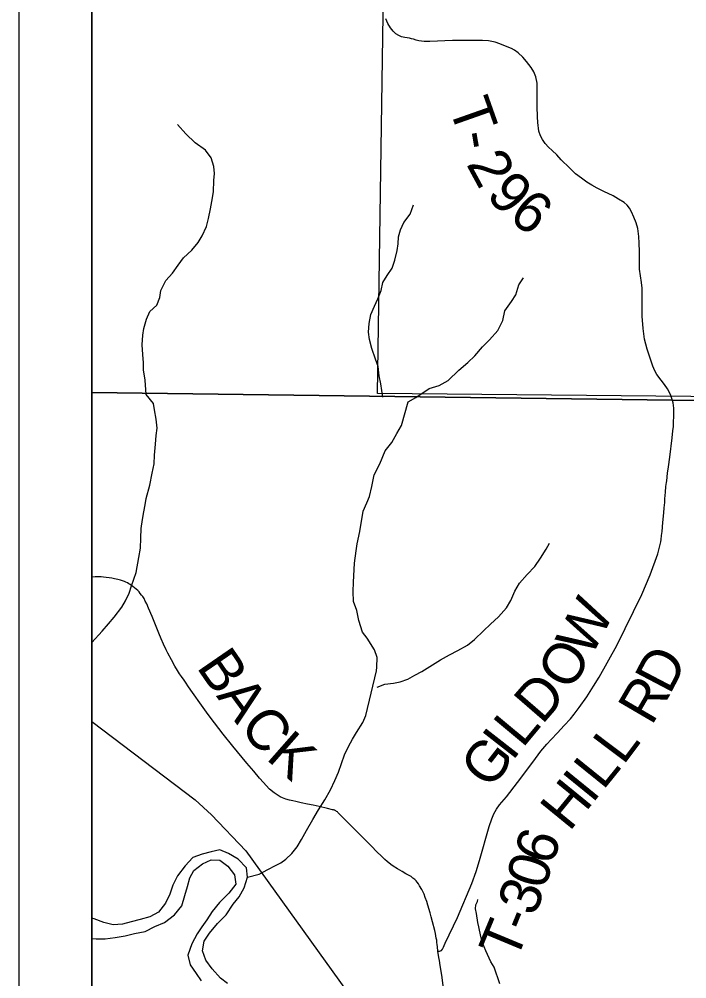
# Model space of a CAD drawing. Extents: x 0 to 34, y -8.9 to 22.
# Drawn here: x 23.617 to 24.538, y 18.53 to 19.856 of the extents above; entities that cross this region are included whole.
import ezdxf

# ---------------------------------------------------------------- set-up
doc = ezdxf.new("R2010")
doc.units = 0
for name, color, linetype in [('GM_X_Corporation', 7, 'Continuous'), ('GM_X_Major_River', 7, 'Continuous'), ('GM_X_Minor_River', 7, 'Continuous'), ('GM_X_Rail_Line', 7, 'Continuous'), ('GM_X_Township_Road', 7, 'Continuous'), ('GM_X_Township_Road_Text', 7, 'Continuous'), ('SH_Data', 7, 'Continuous')]:
    doc.layers.add(name, color=color, linetype=linetype)

msp = doc.modelspace()

# ---------------------------------------------------------------- linework, layer by layer
at = {"layer": 'GM_X_Corporation'}
for points in [[(30.5167, 21.4), (23.7167, 21.4), (23.7167, 19.34), (24.5181, 19.3295), (25.0504, 19.3237), (25.1066, 19.3232), (25.1068, 18.8675), (25.1136, 18.8385), (25.1229, 18.6966), (25.125, 18.6354), (25.1216, 18.6194), (25.1124, 18.5932), (25.1045, 18.3117), (25.2083, 18.3108), (25.7381, 18.312), (26.1399, 18.3037), (26.1391, 17.8847), (26.1361, 17.3278)], [(23.7167, 21.3241), (23.7167, 19.34), (24.5181, 19.3295), (25.0504, 19.3237), (25.1066, 19.3232), (25.1068, 18.8675), (25.1136, 18.8385), (25.1229, 18.6966), (25.125, 18.6354), (25.1216, 18.6194), (25.1124, 18.5932), (25.1045, 18.3117), (25.2083, 18.3108), (25.7381, 18.312), (26.1399, 18.3037), (26.1391, 17.8847), (26.1361, 17.3278)], [(26.1361, 17.3278), (26.1391, 17.8847), (26.1399, 18.3037), (25.7381, 18.312), (25.2083, 18.3108), (25.1045, 18.3117), (25.1124, 18.5932), (25.1216, 18.6194), (25.125, 18.6354), (25.1229, 18.6966), (25.1136, 18.8385), (25.1068, 18.8675), (25.1066, 19.3232), (25.0504, 19.3237), (24.5181, 19.3295), (23.7167, 19.34), (23.7167, 14.6)]]:
    msp.add_lwpolyline(points, dxfattribs=at)
for points in [[(25.1285, 20.3218), (25.1197, 19.3292), (24.1109, 19.3387), (24.1258, 20.3236)], [(23.7167, 19.34), (23.7167, 15.9913), (24.0651, 15.9828), (24.2771, 15.9807), (24.8268, 15.964), (25.6785, 15.9418), (25.7922, 15.939), (26.1186, 15.9366), (26.135, 17.3055), (26.1361, 17.3278), (26.1391, 17.8847), (26.1399, 18.3037), (25.7381, 18.312), (25.2083, 18.3108), (25.1045, 18.3117), (25.1124, 18.5932), (25.1216, 18.6194), (25.125, 18.6354), (25.1229, 18.6966), (25.1136, 18.8385), (25.1068, 18.8675), (25.1066, 19.3232), (25.0504, 19.3237), (24.5181, 19.3295)]]:
    msp.add_lwpolyline(points, close=True, dxfattribs=at)
at = {"layer": 'GM_X_Major_River'}
for points in [[(23.9043, 18.5242), (23.8944, 18.5313), (23.8828, 18.544), (23.874, 18.5564), (23.8696, 18.5693), (23.8721, 18.5822), (23.8791, 18.5937), (23.8903, 18.6067), (23.9023, 18.619), (23.9119, 18.6335), (23.9202, 18.6435), (23.9272, 18.6561), (23.9319, 18.671), (23.9302, 18.6835), (23.9187, 18.6958), (23.9057, 18.7036), (23.8935, 18.7084), (23.8814, 18.7056), (23.8693, 18.7024), (23.8565, 18.698), (23.8456, 18.6865), (23.8352, 18.6727), (23.8289, 18.6597), (23.8246, 18.6472), (23.8187, 18.6349), (23.809, 18.6227), (23.7969, 18.6161), (23.7837, 18.6125), (23.7712, 18.6093), (23.7592, 18.6057), (23.7463, 18.6048), (23.7333, 18.6084), (23.72, 18.6131), (23.7167, 18.6144)], [(23.7167, 18.5863), (23.7227, 18.5855), (23.7352, 18.5856), (23.7492, 18.5874), (23.7628, 18.5898), (23.776, 18.593), (23.7904, 18.5959), (23.8039, 18.6029), (23.8171, 18.608), (23.831, 18.6188), (23.8411, 18.6314), (23.8454, 18.6455), (23.8487, 18.6581), (23.8523, 18.6699), (23.8575, 18.6798), (23.8695, 18.6891), (23.8815, 18.6946), (23.8937, 18.6944), (23.9044, 18.6862), (23.9137, 18.6738), (23.9157, 18.6613), (23.9061, 18.6486), (23.893, 18.6359), (23.8829, 18.6233), (23.8755, 18.6118), (23.8688, 18.6022), (23.8621, 18.5927), (23.8547, 18.5789), (23.8496, 18.5629), (23.8524, 18.5497), (23.8609, 18.5377), (23.8679, 18.5275)]]:
    msp.add_lwpolyline(points, dxfattribs=at)
at = {"layer": 'GM_X_Minor_River'}
for points in [[(23.792, 19.3372), (23.7904, 19.3573), (23.7884, 19.3713), (23.788, 19.3808), (23.7872, 19.3925), (23.7863, 19.4058), (23.7874, 19.4191), (23.7888, 19.4285), (23.7922, 19.4411), (23.797, 19.4521), (23.8068, 19.4605), (23.8106, 19.4712), (23.812, 19.481), (23.8191, 19.4947), (23.8282, 19.5047), (23.8361, 19.5157), (23.8436, 19.526), (23.8549, 19.5367), (23.8636, 19.547), (23.8692, 19.5565), (23.8752, 19.5694), (23.8778, 19.5801), (23.8808, 19.5938), (23.8826, 19.6036), (23.8848, 19.6173), (23.8854, 19.6329), (23.8861, 19.6423), (23.8853, 19.6522), (23.8818, 19.6643), (23.8738, 19.6749), (23.8597, 19.6846), (23.8467, 19.6971), (23.8352, 19.7103)], [(24.1186, 19.3336), (24.1159, 19.3522), (24.1135, 19.3631), (24.1119, 19.376), (24.1084, 19.3859), (24.1034, 19.4006), (24.1003, 19.4131), (24.0987, 19.4234), (24.0998, 19.4351), (24.1019, 19.4477), (24.1072, 19.4594), (24.1117, 19.4693), (24.1162, 19.4811), (24.1187, 19.4921), (24.1244, 19.5017), (24.1315, 19.5116), (24.1352, 19.523), (24.1382, 19.5359), (24.1397, 19.5454), (24.14, 19.5549), (24.1429, 19.5647), (24.1474, 19.5746), (24.1561, 19.5864), (24.1609, 19.599)], [(24.1638, 19.3331), (24.1824, 19.3454), (24.196, 19.3496), (24.2085, 19.3566), (24.2232, 19.3707), (24.2357, 19.3814), (24.2455, 19.3906), (24.256, 19.4031), (24.2658, 19.4127), (24.2771, 19.4257), (24.2839, 19.4394), (24.2868, 19.453), (24.2959, 19.4656), (24.3019, 19.4751), (24.306, 19.4888), (24.3127, 19.4983)], [(23.7167, 18.9947), (23.7312, 19.0107), (23.7401, 19.0207), (23.7476, 19.0296), (23.7584, 19.0438), (23.7632, 19.0526), (23.7684, 19.0629), (23.7717, 19.0732), (23.7783, 19.0916), (23.7818, 19.1121), (23.7842, 19.1251), (23.7844, 19.1387), (23.785, 19.1524), (23.7867, 19.1646), (23.7888, 19.1752), (23.7906, 19.1848), (23.792, 19.1935), (23.797, 19.2122), (23.8002, 19.2286), (23.8027, 19.2415), (23.8033, 19.2533), (23.8046, 19.2685), (23.8059, 19.2807), (23.8069, 19.2909), (23.8056, 19.3034), (23.8035, 19.3159), (23.8022, 19.325), (23.792, 19.3372)], [(24.1311, 19.2711), (24.138, 19.2836), (24.1442, 19.2945), (24.1535, 19.3271), (24.1638, 19.3331)], [(24.1099, 18.9558), (24.1102, 18.961), (24.1108, 18.974), (24.1072, 18.9845), (24.0967, 19.0007), (24.0905, 19.009), (24.0853, 19.0252), (24.0825, 19.0388), (24.0781, 19.0513), (24.0775, 19.0653), (24.0781, 19.0782), (24.0792, 19.1045), (24.0816, 19.1212), (24.083, 19.1311), (24.0869, 19.1482), (24.0915, 19.176), (24.0966, 19.1875), (24.0999, 19.1963), (24.1031, 19.2104), (24.1063, 19.2264), (24.1145, 19.2417), (24.1218, 19.2596), (24.1311, 19.2711)], [(24.1105, 18.9333), (24.1213, 18.9372), (24.133, 18.9387), (24.1426, 18.9403), (24.1529, 18.9441), (24.1627, 18.9499), (24.1723, 18.955), (24.198, 18.9709), (24.2104, 18.9778), (24.2221, 18.9839), (24.2352, 18.9911), (24.2451, 18.9992), (24.2574, 19.011), (24.2669, 19.0202), (24.2779, 19.0302), (24.2891, 19.0428), (24.2953, 19.0529), (24.3008, 19.0657), (24.307, 19.0766), (24.3178, 19.0888), (24.3282, 19.0999), (24.3363, 19.1111), (24.3441, 19.1239), (24.3486, 19.1321)], [(23.9319, 18.671), (23.9479, 18.6748), (23.9596, 18.6814), (23.9705, 18.6869), (23.9777, 18.6908), (23.9848, 18.6958), (23.993, 18.7036), (24.0004, 18.7128), (24.0063, 18.7228), (24.0133, 18.7354), (24.0218, 18.7504), (24.0299, 18.7638), (24.0384, 18.7776), (24.0461, 18.7914), (24.0524, 18.8044), (24.0571, 18.8159), (24.0658, 18.8396), (24.0709, 18.8511), (24.0764, 18.8614), (24.082, 18.8706), (24.0908, 18.8844), (24.0952, 18.894), (24.1099, 18.9558)], [(24.2801, 18.5235), (24.2721, 18.5465), (24.2674, 18.5537), (24.2607, 18.5691), (24.2583, 18.5748), (24.2555, 18.5816), (24.2535, 18.5891), (24.251, 18.6024), (24.2498, 18.6081), (24.2476, 18.6206), (24.2464, 18.627), (24.2467, 18.6327), (24.2489, 18.6373), (24.2496, 18.64)]]:
    msp.add_lwpolyline(points, dxfattribs=at)
at = {"layer": 'GM_X_Rail_Line'}
msp.add_lwpolyline([(23.7167, 18.8857), (23.8593, 18.7777), (23.8822, 18.757), (23.9293, 18.7071), (24.1486, 18.4026)], dxfattribs=at)
at = {"layer": 'GM_X_Township_Road'}
for points in [[(24.1581, 19.8286), (24.1552, 19.8295), (24.1488, 19.8304), (24.1444, 19.8313), (24.1406, 19.8328), (24.1366, 19.8354), (24.1328, 19.8391), (24.1291, 19.8437), (24.1256, 19.8498), (24.1224, 19.856)], [(24.5183, 19.329), (24.5154, 19.3373), (24.5114, 19.345), (24.5071, 19.3513), (24.5028, 19.3571), (24.4968, 19.3649), (24.4938, 19.37), (24.491, 19.3766), (24.4834, 19.3999), (24.4795, 19.4135), (24.4776, 19.4284), (24.4763, 19.4453), (24.4764, 19.4673), (24.4764, 19.484), (24.4756, 19.4921), (24.4729, 19.5103), (24.4727, 19.5349), (24.4722, 19.5461), (24.4716, 19.5554), (24.4703, 19.5667), (24.4679, 19.5744), (24.4647, 19.5822), (24.4615, 19.5897), (24.4589, 19.5948), (24.4559, 19.5985), (24.4514, 19.6022), (24.4439, 19.6069), (24.4364, 19.6114), (24.4237, 19.6175), (24.4145, 19.622), (24.4069, 19.6264), (24.4002, 19.6306), (24.3925, 19.6359), (24.3846, 19.642), (24.3759, 19.6502), (24.3644, 19.6613), (24.3588, 19.6684), (24.352, 19.6742), (24.347, 19.679), (24.3423, 19.6841), (24.3387, 19.6895), (24.336, 19.6944), (24.3338, 19.7008), (24.3324, 19.7129), (24.3318, 19.7206), (24.3316, 19.7352), (24.3313, 19.767), (24.3298, 19.7758), (24.3267, 19.7827), (24.3234, 19.7886), (24.32, 19.793), (24.3166, 19.7973), (24.3118, 19.8032), (24.3052, 19.8091), (24.3002, 19.8127), (24.2959, 19.8149), (24.2901, 19.8174), (24.2801, 19.8214), (24.2734, 19.8236), (24.2687, 19.8248), (24.2643, 19.8255), (24.2559, 19.8262), (24.2453, 19.8262), (24.227, 19.8259), (24.2146, 19.8259), (24.1832, 19.8247), (24.1754, 19.8248), (24.1682, 19.8255), (24.1643, 19.8265), (24.161, 19.8278), (24.1581, 19.8286)], [(24.1946, 18.5684), (24.1969, 18.5684), (24.1995, 18.5694), (24.2007, 18.5714), (24.2021, 18.5743), (24.203, 18.5764), (24.2044, 18.5797), (24.2215, 18.6153), (24.2411, 18.6621), (24.2472, 18.6784), (24.2519, 18.6936), (24.265, 18.7409), (24.2687, 18.7513), (24.2717, 18.7584), (24.2754, 18.7647), (24.2796, 18.7709), (24.289, 18.7817), (24.3042, 18.8013), (24.3253, 18.8297), (24.3367, 18.8448), (24.3447, 18.8545), (24.3508, 18.861), (24.3596, 18.8703), (24.3686, 18.88), (24.3776, 18.8896), (24.3826, 18.8958), (24.3894, 18.9049), (24.3999, 18.9199), (24.4094, 18.9345), (24.4169, 18.947), (24.4412, 18.9906), (24.4761, 19.0613), (24.4875, 19.0885), (24.4978, 19.1174), (24.5022, 19.1337), (24.5025, 19.1371), (24.5031, 19.1425), (24.5038, 19.1482), (24.5048, 19.1606), (24.5061, 19.1741), (24.5069, 19.1808), (24.5075, 19.1882), (24.5078, 19.1931), (24.5085, 19.2023), (24.5092, 19.2103), (24.51, 19.2158), (24.5103, 19.2182), (24.5115, 19.2287), (24.5127, 19.2373), (24.5147, 19.2508), (24.5176, 19.2774), (24.5188, 19.2872), (24.5194, 19.293), (24.5196, 19.2969), (24.5198, 19.3009), (24.52, 19.3055), (24.52, 19.3106), (24.52, 19.3162), (24.5199, 19.3186), (24.5196, 19.322), (24.519, 19.3256), (24.5183, 19.329)], [(24.1946, 18.5684), (24.1939, 18.5745), (24.1936, 18.5776), (24.1932, 18.5806), (24.1928, 18.5837), (24.1923, 18.5867), (24.1912, 18.5928), (24.1902, 18.597), (24.1871, 18.609), (24.1851, 18.6162), (24.1836, 18.6216), (24.1805, 18.6323), (24.179, 18.637), (24.177, 18.6429), (24.1753, 18.6475), (24.1723, 18.6537), (24.1692, 18.659), (24.1676, 18.6616), (24.166, 18.6637), (24.1644, 18.6656), (24.1626, 18.6674), (24.16, 18.6696), (24.1574, 18.6715), (24.1546, 18.6733), (24.1504, 18.6756), (24.145, 18.6786), (24.1385, 18.6823), (24.1328, 18.686), (24.1293, 18.6885), (24.1246, 18.6925), (24.1213, 18.6954), (24.118, 18.6986), (24.1088, 18.7073), (24.104, 18.7122), (24.0906, 18.726), (24.0814, 18.7352), (24.066, 18.7506), (24.0566, 18.76), (24.0557, 18.7609), (24.0547, 18.7617), (24.0538, 18.7623), (24.0529, 18.7628), (24.0521, 18.7631), (24.0512, 18.7634), (24.0503, 18.7636), (24.0492, 18.7639), (24.0423, 18.7655), (24.0308, 18.7683), (24.0224, 18.7702), (24.0144, 18.7718), (24.0059, 18.7736), (23.9986, 18.7751), (23.9944, 18.7761), (23.9896, 18.7772), (23.9848, 18.7786), (23.9802, 18.7803), (23.9768, 18.7819), (23.9725, 18.7843), (23.9685, 18.7872), (23.9623, 18.7925), (23.9575, 18.7974), (23.9537, 18.8015), (23.9484, 18.8075), (23.9403, 18.817), (23.9308, 18.8284), (23.9113, 18.8517), (23.8981, 18.8682), (23.886, 18.8839), (23.8775, 18.8954), (23.8681, 18.9085), (23.8558, 18.9257), (23.8501, 18.9338), (23.8461, 18.9399), (23.8441, 18.9429), (23.8406, 18.948), (23.8381, 18.9516), (23.8351, 18.9563), (23.8316, 18.9622), (23.8267, 18.9708), (23.8218, 18.9802), (23.8196, 18.9846), (23.8159, 18.9925), (23.8128, 18.9999), (23.8095, 19.0079), (23.8, 19.0309), (23.7951, 19.0423), (23.7926, 19.0481), (23.7907, 19.0521), (23.7889, 19.0554), (23.7871, 19.0582), (23.7855, 19.0603), (23.7836, 19.0627), (23.782, 19.0646), (23.7802, 19.0665), (23.778, 19.0685), (23.7758, 19.0705), (23.7737, 19.0721), (23.7717, 19.0736), (23.7696, 19.075), (23.7679, 19.076), (23.7659, 19.0771), (23.7639, 19.0781), (23.7618, 19.079), (23.7593, 19.0798), (23.7566, 19.0807), (23.7529, 19.0818), (23.7507, 19.0823), (23.7482, 19.0829), (23.7447, 19.0836), (23.7409, 19.0842), (23.7368, 19.0847), (23.7328, 19.0852), (23.7298, 19.0854), (23.7264, 19.0855), (23.7217, 19.0854), (23.7174, 19.0849), (23.7167, 19.0847)], [(24.2021, 18.5174), (24.1998, 18.5356), (24.1976, 18.549), (24.1966, 18.5557), (24.1958, 18.5599), (24.1946, 18.5684)]]:
    msp.add_lwpolyline(points, dxfattribs=at)
at = {"layer": 'SH_Data'}
for points in [[(23.6167, 21.5), (30.6167, 21.5), (30.6167, 14.5), (23.6167, 14.5)], [(23.7167, 21.4), (30.5167, 21.4), (30.5167, 14.6), (23.7167, 14.6)]]:
    msp.add_lwpolyline(points, close=True, dxfattribs=at)

# ---------------------------------------------------------------- texts
at = {"layer": 'GM_X_Township_Road_Text'}
for s, rotation, p in [('T', 289.469, (24.2089, 19.7352)), ('-', 279.8371, (24.2224, 19.6975)), ('2', 298.4795, (24.233, 19.6556)), ('9', 313.9436, (24.2595, 19.6114)), ('6', 321.8, (24.2901, 19.5805)), ('W', 62.4239, (24.4054, 18.9725)), ('O', 58.1517, (24.3767, 18.926)), ('B', 304.5377, (23.8604, 18.9611)), ('D', 62.2872, (24.5143, 18.9215)), ('A', 306.3158, (23.8879, 18.921)), ('D', 49.1043, (24.3382, 18.8803)), ('R', 59.6788, (24.4894, 18.8788)), ('C', 308.7513, (23.9192, 18.8787)), ('L', 50.2136, (24.3112, 18.8479)), ('K', 318.6656, (23.9558, 18.8345)), ('I', 52.0216, (24.2971, 18.8299)), ('L', 53.0507, (24.4503, 18.8244)), ('G', 52.2209, (24.2665, 18.7904)), ('L', 51.1093, (24.4223, 18.7897)), ('I', 50.8636, (24.4074, 18.7714)), ('H', 50.8003, (24.3758, 18.7326)), ('6', 71.2014, (24.3519, 18.6853)), ('0', 73.1596, (24.3419, 18.6523)), ('3', 68.8954, (24.3278, 18.6152)), ('-', 67.7199, (24.3185, 18.5925)), ('T', 67.4035, (24.302, 18.5529))]:
    msp.add_text(s, height=0.0568, rotation=rotation, dxfattribs=at).set_placement(p)

doc.saveas('drawing.dxf')
